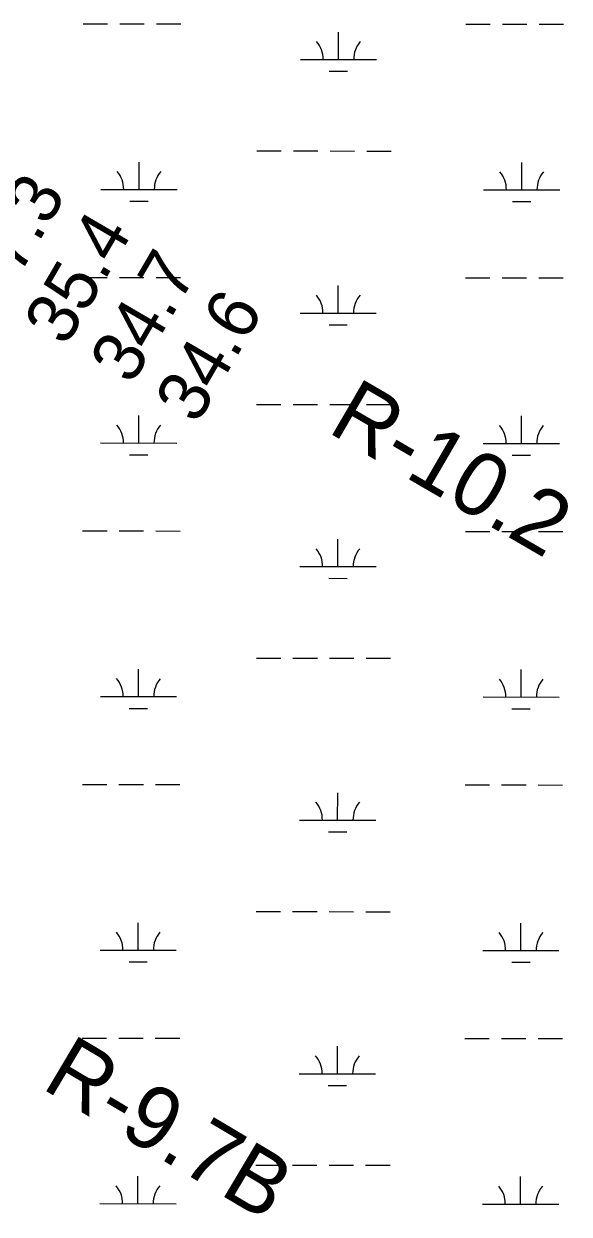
# Model space of a CAD drawing. Extents: x 3148686 to 3186545, y 916144 to 941516.
# Drawn here: x 3159963 to 3160679, y 925065 to 926627 of the extents above; entities that cross this region are included whole.
import ezdxf

# ---------------------------------------------------------------- set-up
doc = ezdxf.new("R2010")
doc.units = 0
for name, color, linetype in [('V-RIVR-RANG', 7, 'Continuous'), ('V-RIVR-RANG-IDEN', 7, 'Continuous'), ('V-WETL-SWMP', 7, 'Continuous')]:
    doc.layers.add(name, color=color, linetype=linetype)

msp = doc.modelspace()

# ---------------------------------------------------------------- linework, layer by layer
at = {"layer": 'V-WETL-SWMP'}
for p, q in [((3160041.2, 926627.1), (3160073.2, 926627.1)), ((3160089.2, 926627.1), (3160121.2, 926627)), ((3160137.2, 926627), (3160169.2, 926627)), ((3160543.1, 926626.6), (3160575.1, 926626.6)), ((3160591.1, 926626.5), (3160623.1, 926626.5)), ((3160639.1, 926626.5), (3160671.1, 926626.5)), ((3160376, 926580.3), (3160376, 926616.3)), ((3160326, 926580.4), (3160426, 926580.3)), ((3160364, 926564.9), (3160388, 926564.9)), ((3160269, 926460.4), (3160301, 926460.3)), ((3160317, 926460.3), (3160349, 926460.3)), ((3160365, 926460.3), (3160397, 926460.2)), ((3160413, 926460.2), (3160445, 926460.2)), ((3160114.4, 926409.8), (3160114.4, 926445.8)), ((3160616.3, 926409.3), (3160616.3, 926445.3)), ((3160064.4, 926409.9), (3160164.4, 926409.7)), ((3160566.3, 926409.3), (3160666.3, 926409.2)), ((3160102.3, 926394.4), (3160126.3, 926394.4)), ((3160604.2, 926393.9), (3160628.2, 926393.8)), ((3160040.8, 926294.4), (3160072.8, 926294.4)), ((3160088.8, 926294.4), (3160120.8, 926294.4)), ((3160136.8, 926294.3), (3160168.8, 926294.3)), ((3160375.6, 926247.7), (3160375.7, 926283.7)), ((3160542.7, 926293.9), (3160574.7, 926293.9)), ((3160590.7, 926293.9), (3160622.7, 926293.8)), ((3160638.7, 926293.8), (3160670.7, 926293.8)), ((3160325.6, 926247.7), (3160425.6, 926247.6)), ((3160363.6, 926232.2), (3160387.6, 926232.2)), ((3160268.6, 926127.7), (3160300.6, 926127.7)), ((3160316.6, 926127.7), (3160348.6, 926127.6)), ((3160364.6, 926127.6), (3160396.6, 926127.6)), ((3160412.6, 926127.6), (3160444.6, 926127.5)), ((3160114, 926077.1), (3160114, 926113.1)), ((3160615.9, 926076.6), (3160615.9, 926112.6)), ((3160064, 926077.2), (3160164, 926077.1)), ((3160565.9, 926076.6), (3160665.9, 926076.5)), ((3160102, 926061.7), (3160126, 926061.7)), ((3160603.9, 926061.2), (3160627.9, 926061.2)), ((3160040.5, 925961.8), (3160072.5, 925961.7)), ((3160088.5, 925961.7), (3160120.5, 925961.7)), ((3160136.5, 925961.7), (3160168.5, 925961.6)), ((3160542.4, 925961.2), (3160574.4, 925961.2)), ((3160590.4, 925961.2), (3160622.4, 925961.2)), ((3160638.4, 925961.1), (3160670.4, 925961.1)), ((3160375.3, 925915), (3160375.3, 925951)), ((3160325.3, 925915), (3160425.3, 925914.9)), ((3160363.3, 925899.6), (3160387.3, 925899.5)), ((3160268.3, 925795), (3160300.3, 925795)), ((3160316.3, 925795), (3160348.3, 925794.9)), ((3160364.3, 925794.9), (3160396.3, 925794.9)), ((3160412.3, 925794.9), (3160444.3, 925794.8)), ((3160113.7, 925744.4), (3160113.7, 925780.4)), ((3160615.6, 925743.9), (3160615.6, 925779.9)), ((3160063.7, 925744.5), (3160163.7, 925744.4)), ((3160565.6, 925744), (3160665.6, 925743.9)), ((3160101.6, 925729), (3160125.6, 925729)), ((3160603.5, 925728.5), (3160627.5, 925728.5)), ((3160040.1, 925629.1), (3160072.1, 925629.1)), ((3160088.1, 925629), (3160120.1, 925629)), ((3160136.1, 925629), (3160168.1, 925629)), ((3160542, 925628.6), (3160574, 925628.5)), ((3160590, 925628.5), (3160622, 925628.5)), ((3160638, 925628.5), (3160670, 925628.4)), ((3160374.9, 925582.3), (3160375, 925618.3)), ((3160324.9, 925582.4), (3160424.9, 925582.3)), ((3160362.9, 925566.9), (3160386.9, 925566.9)), ((3160267.9, 925462.4), (3160299.9, 925462.3)), ((3160315.9, 925462.3), (3160347.9, 925462.3)), ((3160363.9, 925462.3), (3160395.9, 925462.2)), ((3160411.9, 925462.2), (3160443.9, 925462.2)), ((3160113.3, 925411.8), (3160113.3, 925447.8)), ((3160615.2, 925411.2), (3160615.2, 925447.2)), ((3160063.3, 925411.8), (3160163.3, 925411.7)), ((3160565.2, 925411.3), (3160665.2, 925411.2)), ((3160101.3, 925396.4), (3160125.3, 925396.3)), ((3160603.2, 925395.8), (3160627.2, 925395.8)), ((3160039.8, 925296.4), (3160071.8, 925296.4)), ((3160087.8, 925296.4), (3160119.8, 925296.3)), ((3160135.8, 925296.3), (3160167.8, 925296.3)), ((3160374.6, 925249.6), (3160374.6, 925285.6)), ((3160541.7, 925295.9), (3160573.7, 925295.9)), ((3160589.7, 925295.8), (3160621.7, 925295.8)), ((3160637.7, 925295.8), (3160669.7, 925295.8)), ((3160324.6, 925249.7), (3160424.6, 925249.6)), ((3160362.6, 925234.2), (3160386.6, 925234.2)), ((3160267.6, 925129.7), (3160299.6, 925129.6)), ((3160315.6, 925129.6), (3160347.6, 925129.6)), ((3160363.6, 925129.6), (3160395.6, 925129.5)), ((3160411.6, 925129.5), (3160443.6, 925129.5)), ((3160113, 925079.1), (3160113, 925115.1)), ((3160614.9, 925078.6), (3160614.9, 925114.6)), ((3160063, 925079.2), (3160163, 925079)), ((3160564.9, 925078.6), (3160664.9, 925078.5))]:
    msp.add_line(p, q, dxfattribs=at)
for centre, start, end in [((3160320.7, 926580.9), 359.1678, 40.7115), ((3160431.2, 926580.8), 139.1678, 180.7115), ((3160059.1, 926410.3), 359.1678, 40.7115), ((3160169.6, 926410.2), 139.1678, 180.7115), ((3160561, 926409.8), 359.1678, 40.7115), ((3160671.5, 926409.7), 139.1678, 180.7115), ((3160320.4, 926248.2), 359.1678, 40.7115), ((3160430.9, 926248.1), 139.1678, 180.7115), ((3160058.8, 926077.7), 359.1678, 40.7115), ((3160169.2, 926077.5), 139.1678, 180.7115), ((3160560.7, 926077.1), 359.1678, 40.7115), ((3160671.2, 926077), 139.1678, 180.7115), ((3160320, 925915.5), 359.1678, 40.7115), ((3160430.5, 925915.4), 139.1678, 180.7115), ((3160058.4, 925745), 359.1678, 40.7115), ((3160168.9, 925744.9), 139.1678, 180.7115), ((3160560.3, 925744.5), 359.1678, 40.7115), ((3160670.8, 925744.3), 139.1678, 180.7115), ((3160319.7, 925582.8), 359.1678, 40.7115), ((3160430.2, 925582.7), 139.1678, 180.7115), ((3160058.1, 925412.3), 359.1678, 40.7115), ((3160168.5, 925412.2), 139.1678, 180.7115), ((3160560, 925411.8), 359.1678, 40.7115), ((3160670.5, 925411.7), 139.1678, 180.7115), ((3160319.3, 925250.2), 359.1678, 40.7115), ((3160429.8, 925250.1), 139.1678, 180.7115), ((3160057.7, 925079.6), 359.1678, 40.7115), ((3160168.2, 925079.5), 139.1678, 180.7115), ((3160559.6, 925079.1), 359.1678, 40.7115), ((3160670.1, 925079), 139.1678, 180.7115)]:
    msp.add_arc(centre, 35.2, start, end, dxfattribs=at)

# ---------------------------------------------------------------- texts
at = {"layer": 'V-RIVR-RANG'}
for s, p in [('37.3', (3159931.8, 926252.5)), ('35.4', (3160018.3, 926202.3)), ('34.7', (3160104.7, 926152)), ('34.6', (3160190.3, 926100.2))]:
    msp.add_text(s, height=67, rotation=59.7183, dxfattribs=at).set_placement(p)
at = {"layer": 'V-RIVR-RANG-IDEN'}
for s, rotation, p in [('R-10.2', 329.8565, (3160360, 926092.4)), ('R-9.7B', 329.2755, (3159985, 925231.3))]:
    msp.add_text(s, height=83, rotation=rotation, dxfattribs=at).set_placement(p)

doc.saveas('drawing.dxf')
